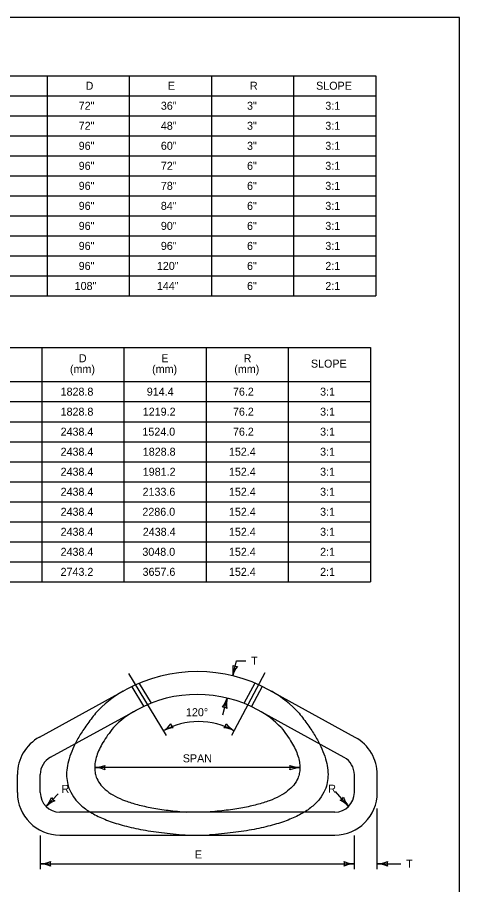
# Model space of a CAD drawing. Extents: x 49991.4 to 50021, y 49987.6 to 50011.4.
# Drawn here: x 50005.3 to 50008.61, y 50004.76 to 50011.26 of the extents above; entities that cross this region are included whole.
import ezdxf

# ---------------------------------------------------------------- set-up
doc = ezdxf.new("R2010")
doc.units = 0
for name, color, linetype in [('Level 1', 7, 'Continuous'), ('Level 2', 7, 'Continuous'), ('Level 3', 7, 'Continuous'), ('Level 4', 7, 'Continuous'), ('Level 5', 7, 'Continuous')]:
    doc.layers.add(name, color=color, linetype=linetype)

msp = doc.modelspace()

# ---------------------------------------------------------------- linework, layer by layer
at = {"layer": 'Level 1'}
for p, q in [((50006.2136, 50006.2727), (50006.3035, 50006.1244)), ((50007.0811, 50006.2747), (50006.9991, 50006.1218)), ((50005.4673, 50005.8698), (50006.1125, 50006.2238)), ((50006.1588, 50006.2477), (50006.2478, 50006.1008)), ((50007.1359, 50006.25), (50007.055, 50006.0994)), ((50007.8326, 50005.868), (50007.1887, 50006.2228)), ((50005.5498, 50005.7192), (50006.195, 50006.0732)), ((50007.7497, 50005.7176), (50007.1058, 50006.0724)), ((50005.3018, 50005.455), (50005.3018, 50005.5902)), ((50005.4735, 50005.455), (50005.4735, 50005.5902)), ((50007.8258, 50005.455), (50007.8258, 50005.5888)), ((50007.9975, 50005.455), (50007.9975, 50005.5888)), ((50007.6788, 50005.3079), (50005.6205, 50005.3079)), ((50005.6205, 50005.1362), (50007.6788, 50005.1362))]:
    msp.add_line(p, q, dxfattribs=at)
msp.add_lwpolyline([(50008.6146, 50011.2628), (50000.3356, 50011.2628), (50000.3356, 50000.0624), (50008.6146, 50000.0624)], close=True, dxfattribs=at)
for centre, radius, start, end in [((50006.6497, 50005.2446), 1.1168, 61.14879, 118.75528), ((50006.6497, 50005.2446), 0.9451, 61.14879, 118.75528), ((50006.5014, 50005.4897), 0.659, 117.69933, 136.79292), ((50006.7979, 50005.4897), 0.659, 43.20708, 62.30067), ((50005.6205, 50005.5902), 0.3188, 118.75791, 180), ((50007.6788, 50005.5887), 0.3188, 0, 61.15429), ((50005.6205, 50005.5902), 0.1471, 118.75791, 180), ((50007.6788, 50005.5887), 0.1471, 0, 61.15429), ((50005.6205, 50005.455), 0.3188, 180, 270), ((50005.6205, 50005.455), 0.1471, 180, 270), ((50007.6788, 50005.455), 0.1471, 270, 0), ((50007.6788, 50005.455), 0.3188, 270, 0), ((50005.654, 50005.2832), 0.1471, 270, 270.00000277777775), ((50007.6453, 50005.2832), 0.1471, 269.99999722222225, 270)]:
    msp.add_arc(centre, radius, start, end, dxfattribs=at)
for points in [[(50006.0211, 50005.9409), (50005.5708, 50005.3838), (50006.5706, 50005.308)], [(50007.2782, 50005.9409), (50007.7285, 50005.3838), (50006.7287, 50005.308)]]:
    msp.add_open_spline(points, degree=2, dxfattribs=at)
at = {"layer": 'Level 2'}
for p, q in [((50001.2166, 50010.8254), (50007.9857, 50010.8254)), ((50005.5242, 50010.8254), (50005.5242, 50009.1754)), ((50006.1395, 50010.8254), (50006.1395, 50009.1754)), ((50006.7549, 50010.8254), (50006.7549, 50009.1754)), ((50007.3703, 50010.8254), (50007.3703, 50009.1754)), ((50007.9857, 50010.8254), (50007.9857, 50009.1754)), ((50001.2166, 50010.6754), (50007.9857, 50010.6754)), ((50001.2166, 50010.5254), (50007.9857, 50010.5254)), ((50001.2166, 50010.3754), (50007.9857, 50010.3754)), ((50001.2166, 50010.2254), (50007.9857, 50010.2254)), ((50001.2166, 50010.0754), (50007.9857, 50010.0754)), ((50001.2166, 50009.9254), (50007.9857, 50009.9254)), ((50001.2166, 50009.7754), (50007.9857, 50009.7754)), ((50001.2166, 50009.6254), (50007.9857, 50009.6254)), ((50001.2166, 50009.4754), (50007.9857, 50009.4754)), ((50001.2166, 50009.3254), (50007.9857, 50009.3254)), ((50001.2166, 50009.1754), (50007.9857, 50009.1754)), ((50001.1776, 50008.788), (50007.9467, 50008.788)), ((50005.4852, 50008.788), (50005.4852, 50007.0334)), ((50006.1005, 50008.788), (50006.1005, 50007.0334)), ((50006.7159, 50008.788), (50006.7159, 50007.0334)), ((50007.3313, 50008.788), (50007.3313, 50007.0334)), ((50007.9467, 50008.788), (50007.9467, 50007.0334)), ((50001.1776, 50008.5334), (50007.9467, 50008.5334)), ((50001.1776, 50008.3834), (50007.9467, 50008.3834)), ((50001.1776, 50008.2334), (50007.9467, 50008.2334)), ((50001.1776, 50008.0834), (50007.9467, 50008.0834)), ((50001.1776, 50007.9334), (50007.9467, 50007.9334)), ((50001.1776, 50007.7834), (50007.9467, 50007.7834)), ((50001.1776, 50007.6334), (50007.9467, 50007.6334)), ((50001.1776, 50007.4834), (50007.9467, 50007.4834)), ((50001.1776, 50007.3334), (50007.9467, 50007.3334)), ((50001.1776, 50007.1834), (50007.9467, 50007.1834)), ((50001.1776, 50007.0334), (50007.9467, 50007.0334))]:
    msp.add_line(p, q, dxfattribs=at)
at = {"layer": 'Level 3'}
for p, q in [((50006.9148, 50006.3295), (50006.9432, 50006.4421)), ((50006.9432, 50006.4421), (50007.0127, 50006.4421)), ((50006.8411, 50006.0381), (50006.8727, 50006.163)), ((50007.418, 50005.6413), (50005.8813, 50005.6413)), ((50005.5167, 50005.3509), (50005.6079, 50005.4444)), ((50007.7827, 50005.351), (50007.6841, 50005.4618)), ((50007.9976, 50004.8812), (50007.9976, 50005.335)), ((50005.4735, 50005.1321), (50005.4735, 50004.8812)), ((50007.8258, 50004.8812), (50007.8258, 50005.1321)), ((50005.4735, 50004.9212), (50007.8258, 50004.9212)), ((50007.9976, 50004.9212), (50008.1736, 50004.9212))]:
    msp.add_line(p, q, dxfattribs=at)
for centre, radius, start, end in [((50006.6863, 50006.3752), 0.233, 348.67749, 7.92734), ((50006.9461, 50006.4538), 0.0548, 237.989, 273.71136), ((50007.1279, 50006.2663), 0.2223, 143.30619, 163.4897), ((50006.6596, 50006.2264), 0.2223, 323.24329, 343.4268), ((50007.1011, 50006.117), 0.233, 168.61459, 187.86444), ((50006.8412, 50006.0387), 0.0548, 57.9261, 93.64846), ((50006.6605, 50005.4475), 0.5392, 60.76231, 119.55494), ((50006.2694, 50006.1131), 0.233, 302.47618, 321.72603), ((50006.506, 50005.9799), 0.0548, 191.78769, 227.51005), ((50006.8119, 50005.9806), 0.0548, 312.92083, 348.64319), ((50007.0403, 50006.1074), 0.2223, 218.23803, 238.42153), ((50006.4965, 50005.7189), 0.2223, 97.10488, 117.28839), ((50006.8203, 50005.7093), 0.233, 63.60933, 82.85918), ((50005.8698, 50005.874), 0.233, 272.82744, 292.07729), ((50005.8698, 50005.874), 0.233, 272.82744, 292.07729), ((50005.8721, 50005.4192), 0.2223, 67.45614, 87.63965), ((50005.8721, 50005.4192), 0.2223, 67.45614, 87.63965), ((50006.0095, 50005.6413), 0.0548, 162.13895, 197.86131), ((50006.0095, 50005.6413), 0.0548, 162.13895, 197.86131), ((50007.4272, 50005.8634), 0.2223, 247.45614, 267.63965), ((50007.2898, 50005.6413), 0.0548, 342.13895, 17.86131), ((50007.4295, 50005.4086), 0.233, 92.82744, 112.07729), ((50005.3421, 50005.5052), 0.233, 318.52936, 337.77921), ((50005.6692, 50005.1892), 0.2223, 113.15806, 133.34156), ((50005.6062, 50005.4426), 0.0548, 207.84086, 243.56322), ((50007.6975, 50005.4467), 0.0548, 293.8047, 329.52706), ((50007.6165, 50005.1877), 0.233, 44.49319, 63.74304), ((50007.9547, 50005.4918), 0.2223, 199.12189, 219.3054), ((50005.462, 50005.1539), 0.233, 272.82731, 292.07716), ((50005.4643, 50004.699), 0.2223, 67.45601, 87.63952), ((50005.6017, 50004.9212), 0.0548, 162.13882, 197.86118), ((50007.8349, 50005.1433), 0.2223, 247.45601, 267.63952), ((50007.6976, 50004.9212), 0.0548, 342.13882, 17.86118), ((50007.8373, 50004.6885), 0.233, 92.82731, 112.07716), ((50007.9861, 50005.1539), 0.233, 272.82731, 292.07716), ((50007.9884, 50004.699), 0.2223, 67.45601, 87.63952), ((50008.1258, 50004.9212), 0.0548, 162.13882, 197.86118)]:
    msp.add_arc(centre, radius, start, end, dxfattribs=at)
at = {"layer": 'Level 4'}
for centre, start, end in [((50006.5014, 50005.4897), 119.38613, 137.67784), ((50006.7979, 50005.4897), 42.32009, 60.6556)]:
    msp.add_arc(centre, 0.8307, start, end, dxfattribs=at)
for points in [[(50005.8876, 50006.0488), (50005.2316, 50005.2373), (50006.5576, 50005.1368)], [(50007.4117, 50006.0488), (50008.0677, 50005.2373), (50006.7417, 50005.1368)]]:
    msp.add_open_spline(points, degree=2, dxfattribs=at)
at = {"layer": 'Level 5'}
for p, q in [((50006.134, 50006.346), (50006.4153, 50005.8823)), ((50007.1558, 50006.3509), (50006.905, 50005.8827))]:
    msp.add_line(p, q, dxfattribs=at)

# ---------------------------------------------------------------- texts
at = {"layer": 'Level 2'}
for s, p in [('D', (50005.8131, 50010.7204)), ('E', (50006.4288, 50010.7204)), ('R', (50007.0439, 50010.7204)), ('SLOPE', (50007.5396, 50010.7204)), ('72"', (50005.7612, 50010.5704)), ('36"', (50006.3766, 50010.5704)), ('3"', (50007.022, 50010.5704)), ('3:1', (50007.6084, 50010.5704)), ('72"', (50005.7612, 50010.4204)), ('48"', (50006.3766, 50010.4204)), ('3"', (50007.022, 50010.4204)), ('3:1', (50007.6084, 50010.4204)), ('96"', (50005.7612, 50010.2704)), ('60"', (50006.3767, 50010.2704)), ('3"', (50007.022, 50010.2704)), ('3:1', (50007.6084, 50010.2704)), ('96"', (50005.7612, 50010.1204)), ('72"', (50006.3766, 50010.1204)), ('6"', (50007.022, 50010.1204)), ('3:1', (50007.6084, 50010.1204)), ('96"', (50005.7612, 50009.9704)), ('78"', (50006.3766, 50009.9704)), ('6"', (50007.022, 50009.9704)), ('3:1', (50007.6084, 50009.9704)), ('96"', (50005.7612, 50009.8204)), ('84"', (50006.3765, 50009.8204)), ('6"', (50007.022, 50009.8204)), ('3:1', (50007.6084, 50009.8204)), ('96"', (50005.7612, 50009.6704)), ('90"', (50006.3767, 50009.6704)), ('6"', (50007.022, 50009.6704)), ('3:1', (50007.6084, 50009.6704)), ('96"', (50005.7612, 50009.5204)), ('96"', (50006.3766, 50009.5204)), ('6"', (50007.022, 50009.5204)), ('3:1', (50007.6084, 50009.5204)), ('96"', (50005.7611, 50009.3704)), ('120"', (50006.3467, 50009.3704)), ('6"', (50007.022, 50009.3704)), ('2:1', (50007.6084, 50009.3704)), ('108"', (50005.7311, 50009.2204)), ('144"', (50006.3467, 50009.2204)), ('6"', (50007.022, 50009.2204)), ('2:1', (50007.6084, 50009.2204)), ('D', (50005.7624, 50008.6786)), ('E', (50006.3802, 50008.6786)), ('R', (50006.9967, 50008.6786)), ('SLOPE', (50007.5006, 50008.6384)), ('(mm)', (50005.6958, 50008.5982)), ('(mm)', (50006.3112, 50008.5982)), ('(mm)', (50006.9266, 50008.5982)), ('1828.8', (50005.6258, 50008.4284)), ('914.4', (50006.2712, 50008.4284)), ('76.2', (50006.9166, 50008.4284)), ('3:1', (50007.5694, 50008.4284)), ('1828.8', (50005.6258, 50008.2784)), ('1219.2', (50006.2412, 50008.2784)), ('76.2', (50006.9166, 50008.2784)), ('3:1', (50007.5694, 50008.2784)), ('2438.4', (50005.6258, 50008.1284)), ('1524.0', (50006.2383, 50008.1284)), ('76.2', (50006.9166, 50008.1284)), ('3:1', (50007.5694, 50008.1284)), ('2438.4', (50005.6258, 50007.9784)), ('1828.8', (50006.2412, 50007.9784)), ('152.4', (50006.8866, 50007.9784)), ('3:1', (50007.5694, 50007.9784)), ('2438.4', (50005.6258, 50007.8284)), ('1981.2', (50006.2412, 50007.8284)), ('152.4', (50006.8866, 50007.8284)), ('3:1', (50007.5694, 50007.8284)), ('2438.4', (50005.6258, 50007.6784)), ('2133.6', (50006.2395, 50007.6784)), ('152.4', (50006.8866, 50007.6784)), ('3:1', (50007.5694, 50007.6784)), ('2438.4', (50005.6258, 50007.5284)), ('2286.0', (50006.2383, 50007.5284)), ('152.4', (50006.8866, 50007.5284)), ('3:1', (50007.5694, 50007.5284)), ('2438.4', (50005.6258, 50007.3784)), ('2438.4', (50006.2412, 50007.3784)), ('152.4', (50006.8866, 50007.3784)), ('3:1', (50007.5694, 50007.3784)), ('2438.4', (50005.6257, 50007.2284)), ('3048.0', (50006.2383, 50007.2284)), ('152.4', (50006.8866, 50007.2284)), ('2:1', (50007.5694, 50007.2284)), ('2743.2', (50005.6257, 50007.0784)), ('3657.6', (50006.2397, 50007.0784)), ('152.4', (50006.8866, 50007.0784)), ('2:1', (50007.5694, 50007.0784)), ('T', (50007.0527, 50006.4121)), ('120°', (50006.5649, 50006.0267)), ('SPAN', (50006.541, 50005.6813)), ('R', (50005.6325, 50005.4524)), ('R', (50007.6305, 50005.4534)), ('E', (50006.6313, 50004.9612)), ('T', (50008.2136, 50004.8912))]:
    msp.add_text(s, height=0.06, dxfattribs=at).set_placement(p)

doc.saveas('drawing.dxf')
